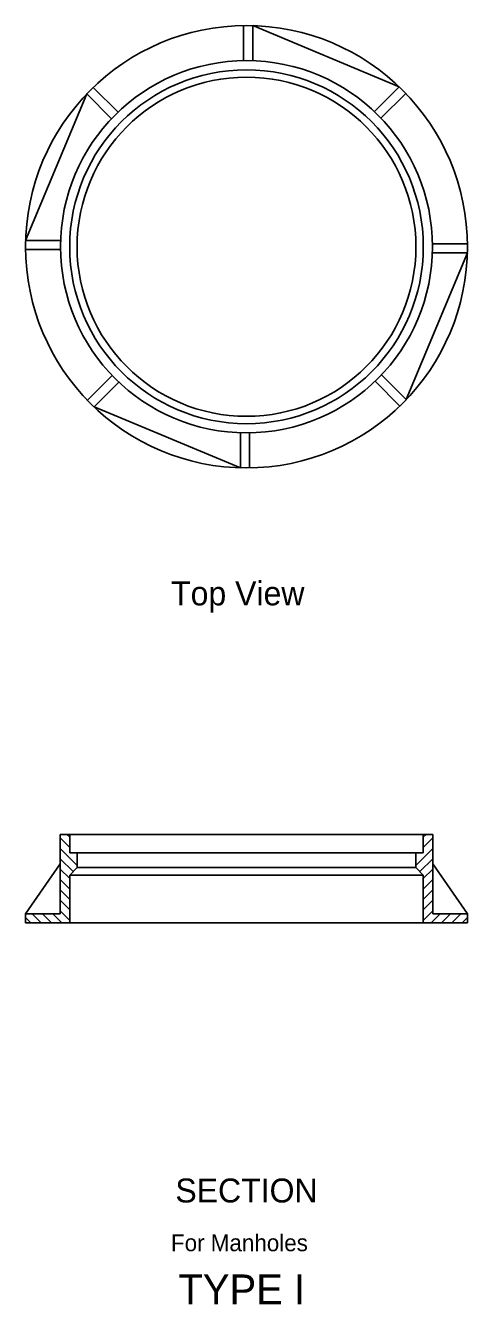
# Model space of a CAD drawing. Extents: x 4851 to 4902, y 9954.5 to 9971.9.
# Drawn here: x 4859.19 to 4861.69, y 9963.67 to 9970.9 of the extents above; entities that cross this region are included whole.
import ezdxf

# ---------------------------------------------------------------- set-up
doc = ezdxf.new("R2010")
doc.units = 0
for name, color, linetype in [('Dimension', 7, 'Continuous'), ('DSText', 7, 'Continuous'), ('SupstrConc', 7, 'Continuous'), ('TextMinor', 7, 'Continuous'), ('TextMisc', 7, 'Continuous')]:
    doc.layers.add(name, color=color, linetype=linetype)

msp = doc.modelspace()

# ---------------------------------------------------------------- linework, layer by layer
at = {"layer": 'Dimension'}
for p, q in [((4860.4263, 9970.7038), (4860.4263, 9970.9017)), ((4860.4784, 9970.7036), (4860.4784, 9970.9016)), ((4859.7159, 9970.4126), (4859.5759, 9970.5526)), ((4861.1664, 9970.4157), (4861.3064, 9970.5557)), ((4859.679, 9970.3759), (4859.539, 9970.5158)), ((4861.2031, 9970.3787), (4861.3431, 9970.5187)), ((4859.3911, 9969.6878), (4859.1931, 9969.6878)), ((4861.4943, 9969.669), (4861.6923, 9969.669)), ((4859.391, 9969.6357), (4859.193, 9969.6357)), ((4861.4941, 9969.6169), (4861.6921, 9969.6169)), ((4859.6831, 9968.9244), (4859.5431, 9968.7844)), ((4859.7199, 9968.8875), (4859.5799, 9968.7475)), ((4861.1697, 9968.892), (4861.3096, 9968.752)), ((4861.2066, 9968.9287), (4861.3466, 9968.7888)), ((4860.4083, 9968.6005), (4860.4083, 9968.4026)), ((4860.4604, 9968.6004), (4860.4604, 9968.4025)), ((4859.3887, 9965.8825), (4859.3883, 9966.3304)), ((4859.4426, 9966.3304), (4859.3883, 9966.3304)), ((4859.4426, 9966.2262), (4859.4426, 9966.3304)), ((4861.4426, 9966.2262), (4861.4426, 9966.3304)), ((4861.4426, 9966.3304), (4861.4969, 9966.3304)), ((4861.4965, 9965.8825), (4861.4969, 9966.3304)), ((4859.4843, 9966.2262), (4859.4426, 9966.2262)), ((4859.4843, 9966.1429), (4859.4843, 9966.2262)), ((4861.4009, 9966.2262), (4861.4426, 9966.2262)), ((4861.4009, 9966.1429), (4861.4009, 9966.2262)), ((4859.4843, 9966.1429), (4859.4426, 9966.1012)), ((4861.4009, 9966.1429), (4861.4426, 9966.1012)), ((4859.4426, 9965.8304), (4859.4426, 9966.1012)), ((4861.4426, 9965.8304), (4861.4426, 9966.1012)), ((4859.3887, 9965.8825), (4859.1926, 9965.8825)), ((4859.1926, 9965.8304), (4859.1926, 9965.8825)), ((4859.4426, 9965.8304), (4859.1926, 9965.8304)), ((4861.4426, 9965.8304), (4861.6926, 9965.8304)), ((4861.4965, 9965.8825), (4861.6926, 9965.8825)), ((4861.6926, 9965.8304), (4861.6926, 9965.8825))]:
    msp.add_line(p, q, dxfattribs=at)
for radius in [1.25, 1.0521, 1, 0.9583]:
    msp.add_circle((4860.4426, 9969.6521), radius, dxfattribs=at)
at = {"layer": 'SupstrConc'}
for p, q in [((4859.4426, 9966.3304), (4861.4426, 9966.3304)), ((4859.4843, 9966.2262), (4861.4009, 9966.2262)), ((4859.1926, 9965.8825), (4859.3884, 9966.1637)), ((4859.4843, 9966.1429), (4861.4009, 9966.1429)), ((4861.6926, 9965.8825), (4861.4968, 9966.1637)), ((4859.4426, 9966.1012), (4861.4426, 9966.1012)), ((4859.4426, 9965.8304), (4861.4426, 9965.8304))]:
    msp.add_line(p, q, dxfattribs=at)
at = {"layer": 'TextMinor'}
for p, q in [((4860.4784, 9970.9016), (4861.3064, 9970.5557)), ((4859.1931, 9969.6878), (4859.539, 9970.5158)), ((4861.6921, 9969.6169), (4861.3466, 9968.7888)), ((4860.4083, 9968.4026), (4859.5799, 9968.7475))]:
    msp.add_line(p, q, dxfattribs=at)
at = {"layer": 'TextMisc'}
for points in [[(4859.4426, 9966.3147), (4859.4268, 9966.3304)], [(4861.4426, 9966.3147), (4861.4584, 9966.3304)], [(4859.4426, 9966.2562), (4859.3883, 9966.3105)], [(4861.4426, 9966.2562), (4861.4969, 9966.3105)], [(4859.4843, 9966.1559), (4859.3884, 9966.2519)], [(4859.4616, 9966.1202), (4859.3884, 9966.1934)], [(4861.4009, 9966.1559), (4861.4968, 9966.2519)], [(4861.4236, 9966.1202), (4861.4968, 9966.1934)], [(4859.4426, 9966.0807), (4859.3885, 9966.1348)], [(4861.4426, 9966.0807), (4861.4967, 9966.1348)], [(4859.4426, 9966.0222), (4859.3885, 9966.0763)], [(4861.4426, 9966.0222), (4861.4967, 9966.0763)], [(4859.4426, 9965.9637), (4859.3886, 9966.0177)], [(4861.4426, 9965.9637), (4861.4966, 9966.0177)], [(4859.4426, 9965.9052), (4859.3887, 9965.9592)], [(4859.4426, 9965.8446), (4859.3887, 9965.8985)], [(4861.4426, 9965.9052), (4861.4965, 9965.9592)], [(4861.4426, 9965.8446), (4861.4965, 9965.8985)], [(4859.2228, 9965.8305), (4859.1926, 9965.8607)], [(4859.2813, 9965.8304), (4859.2292, 9965.8825)], [(4859.3398, 9965.8304), (4859.2877, 9965.8825)], [(4859.3983, 9965.8304), (4859.3462, 9965.8825)], [(4861.4869, 9965.8304), (4861.539, 9965.8825)], [(4861.5454, 9965.8304), (4861.5975, 9965.8825)], [(4861.6039, 9965.8304), (4861.656, 9965.8825)], [(4861.6624, 9965.8305), (4861.6926, 9965.8607)]]:
    msp.add_lwpolyline(points, dxfattribs=at)

# ---------------------------------------------------------------- texts
at = {"layer": 'DSText'}
for s, height, p in [('Top View', 0.13537, (4860.016, 9967.6253)), ('SECTION', 0.13537, (4860.0401, 9964.2505)), ('For Manholes', 0.094762, (4860.0152, 9963.975)), ('TYPE I', 0.16922, (4860.0573, 9963.6744))]:
    msp.add_text(s, height=height, dxfattribs=at).set_placement(p)

doc.saveas('drawing.dxf')
